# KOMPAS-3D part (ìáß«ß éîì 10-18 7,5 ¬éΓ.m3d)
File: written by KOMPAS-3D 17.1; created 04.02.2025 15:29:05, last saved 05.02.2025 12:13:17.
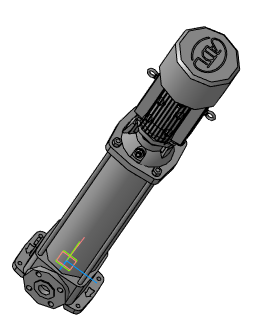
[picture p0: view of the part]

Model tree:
1. Операция без истории:1  (labels: Насос ВМН 10-18 7,5 кВт)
